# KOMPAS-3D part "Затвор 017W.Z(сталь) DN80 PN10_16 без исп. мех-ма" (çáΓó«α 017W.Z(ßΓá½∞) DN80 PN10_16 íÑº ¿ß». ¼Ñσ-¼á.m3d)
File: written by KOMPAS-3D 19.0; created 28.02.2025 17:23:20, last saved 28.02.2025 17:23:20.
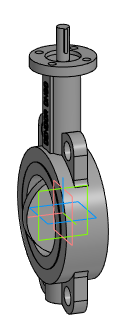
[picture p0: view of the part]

Document properties: Автор: Евгений; Полное имя файла: E:\Dendor Работа Сачек\3D для проекитирвщиков\1.5 Тип 017W.Z Сталь Затвор дисковый поворотный Межфланцевый\stp_Тип 017W.Z(сталь). Затвор без исполн. механизма\Затвор 017W.Z(сталь) DN80 PN10_16 без исп. мех-ма.m3d

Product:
- Part/product: Затвор 017W.Z(сталь) DN80 PN10_16 без исп. мех-ма

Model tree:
1. Операция без истории:1  (labels: Затвор 017W.Z(сталь) DN80 PN10_16 без исп. мех-ма)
